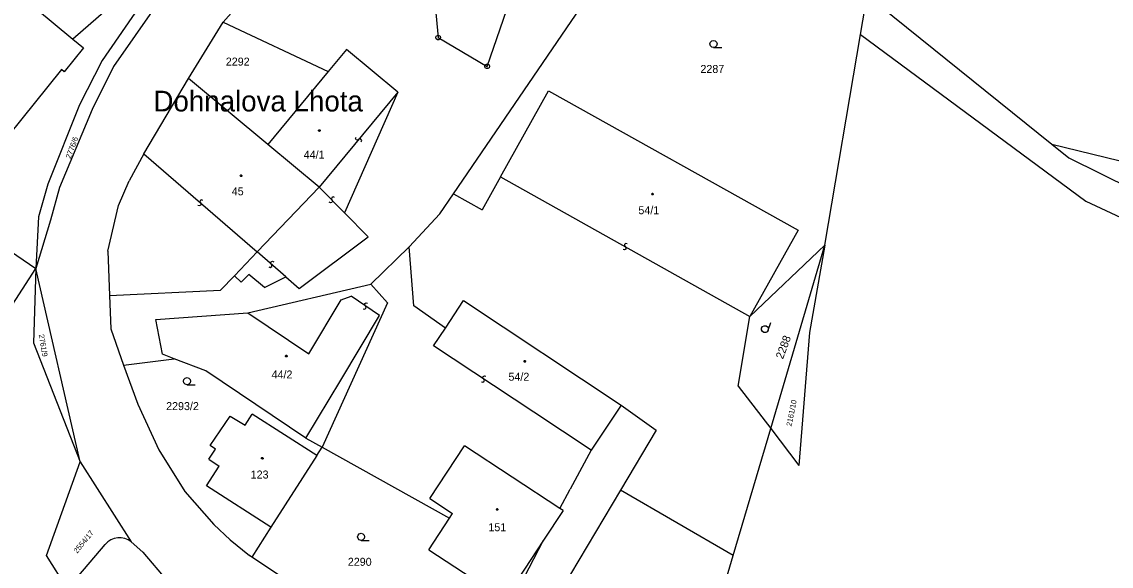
# Model space of a CAD drawing. Extents: x -747792 to -745414, y -1093712 to -1091463.
# Drawn here: x -746688.5 to -746572.8, y -1093115.1 to -1093057.2 of the extents above; entities that cross this region are included whole.
import ezdxf

# ---------------------------------------------------------------- set-up
doc = ezdxf.new("R2010")
doc.units = 0
for name, color, linetype in [('Pracovní_bod JDTM STC_VC', 7, 'Continuous'), ('Pracovní_bod JDTM STC_VC - výška', 7, 'Continuous'), ('Pracovní_bod JDTM STC_VC - číslo', 7, 'Continuous'), ('Pracovní_bod NN - výška', 7, 'Continuous'), ('Pracovní_bod polohopisu', 7, 'Continuous'), ('Pracovní_bod polohopisu - výška', 7, 'Continuous'), ('Pracovní_bod VN - výška', 7, 'Continuous')]:
    doc.layers.add(name, color=color, linetype=linetype)

msp = doc.modelspace()

# ---------------------------------------------------------------- linework, layer by layer
at = {"layer": 'Pracovní_bod JDTM STC_VC - výška'}
for points in [[(-746656.87, -1093068.71), (-746656.82, -1093068.72), (-746656.79, -1093068.76), (-746656.78, -1093068.79), (-746656.79, -1093068.83), (-746656.83, -1093068.87), (-746656.87, -1093068.88), (-746656.92, -1093068.86), (-746656.95, -1093068.83), (-746656.96, -1093068.79), (-746656.95, -1093068.75), (-746656.91, -1093068.71)], [(-746665.19, -1093073.51), (-746665.14, -1093073.52), (-746665.11, -1093073.56), (-746665.1, -1093073.59), (-746665.11, -1093073.64), (-746665.16, -1093073.67), (-746665.19, -1093073.68), (-746665.23, -1093073.66), (-746665.26, -1093073.63), (-746665.27, -1093073.59), (-746665.26, -1093073.54), (-746665.22, -1093073.51)], [(-746621.49, -1093075.46), (-746621.44, -1093075.47), (-746621.42, -1093075.51), (-746621.41, -1093075.54), (-746621.42, -1093075.58), (-746621.46, -1093075.62), (-746621.49, -1093075.62), (-746621.53, -1093075.61), (-746621.57, -1093075.58), (-746621.58, -1093075.54), (-746621.57, -1093075.5), (-746621.52, -1093075.46)], [(-746660.38, -1093092.67), (-746660.33, -1093092.68), (-746660.3, -1093092.72), (-746660.29, -1093092.75), (-746660.3, -1093092.79), (-746660.34, -1093092.83), (-746660.38, -1093092.83), (-746660.43, -1093092.82), (-746660.46, -1093092.79), (-746660.47, -1093092.75), (-746660.46, -1093092.71), (-746660.42, -1093092.67)], [(-746635.04, -1093093.23), (-746634.99, -1093093.24), (-746634.97, -1093093.28), (-746634.96, -1093093.31), (-746634.97, -1093093.35), (-746635.01, -1093093.39), (-746635.04, -1093093.4), (-746635.08, -1093093.38), (-746635.11, -1093093.35), (-746635.12, -1093093.31), (-746635.11, -1093093.27), (-746635.08, -1093093.23)], [(-746662.93, -1093103.53), (-746662.88, -1093103.54), (-746662.85, -1093103.58), (-746662.84, -1093103.61), (-746662.85, -1093103.66), (-746662.9, -1093103.69), (-746662.93, -1093103.7), (-746662.98, -1093103.68), (-746663.01, -1093103.65), (-746663.02, -1093103.61), (-746663.01, -1093103.56), (-746662.97, -1093103.53)], [(-746637.99, -1093108.96), (-746637.94, -1093108.97), (-746637.92, -1093109.01), (-746637.91, -1093109.04), (-746637.92, -1093109.08), (-746637.96, -1093109.12), (-746637.99, -1093109.12), (-746638.03, -1093109.11), (-746638.07, -1093109.08), (-746638.08, -1093109.04), (-746638.07, -1093109), (-746638.02, -1093108.96)]]:
    msp.add_lwpolyline(points, close=True, dxfattribs=at)
at = {"layer": 'Pracovní_bod JDTM STC_VC - číslo'}
for points in [[(-746615.01, -1093059.97), (-746615.2, -1093059.92), (-746615.33, -1093059.78), (-746615.39, -1093059.59), (-746615.33, -1093059.41), (-746615.2, -1093059.27), (-746615.01, -1093059.22), (-746614.82, -1093059.27), (-746614.69, -1093059.41), (-746614.64, -1093059.59), (-746614.69, -1093059.78), (-746614.82, -1093059.92), (-746615.01, -1093059.97), (-746614.14, -1093059.97)], [(-746609.19, -1093090), (-746609.3, -1093090.17), (-746609.47, -1093090.25), (-746609.66, -1093090.24), (-746609.82, -1093090.14), (-746609.91, -1093089.97), (-746609.9, -1093089.77), (-746609.8, -1093089.61), (-746609.62, -1093089.52), (-746609.43, -1093089.53), (-746609.27, -1093089.63), (-746609.18, -1093089.8), (-746609.19, -1093090), (-746608.92, -1093089.17)], [(-746670.93, -1093095.79), (-746671.12, -1093095.74), (-746671.26, -1093095.6), (-746671.31, -1093095.42), (-746671.26, -1093095.23), (-746671.12, -1093095.09), (-746670.93, -1093095.04), (-746670.74, -1093095.09), (-746670.6, -1093095.23), (-746670.56, -1093095.42), (-746670.6, -1093095.6), (-746670.74, -1093095.74), (-746670.93, -1093095.79), (-746670.06, -1093095.79)], [(-746652.44, -1093112.33), (-746652.63, -1093112.28), (-746652.76, -1093112.14), (-746652.82, -1093111.96), (-746652.76, -1093111.77), (-746652.63, -1093111.63), (-746652.44, -1093111.58), (-746652.25, -1093111.63), (-746652.11, -1093111.77), (-746652.07, -1093111.96), (-746652.11, -1093112.14), (-746652.25, -1093112.28), (-746652.44, -1093112.33), (-746651.57, -1093112.33)]]:
    msp.add_lwpolyline(points, dxfattribs=at)
at = {"layer": 'Pracovní_bod NN - výška'}
for points in [[(-746646, -1093040.57), (-746644.26, -1093058.92)], [(-746667.08, -1093057.29), (-746652.89, -1093041.3)], [(-746639.05, -1093061.97), (-746634.9, -1093049.93)], [(-746690.81, -1093052.63), (-746683.06, -1093059.07)], [(-746675.99, -1093052.89), (-746683.06, -1093059.07)], [(-746672.1, -1093052.41), (-746678.75, -1093061.97)], [(-746642.63, -1093075.5), (-746627.61, -1093053.49)], [(-746599.4, -1093058.58), (-746598.7, -1093054.4)], [(-746598.7, -1093054.4), (-746579.06, -1093070.24)], [(-746675.78, -1093055.31), (-746679.93, -1093061.36)], [(-746670.76, -1093063.27), (-746667.08, -1093057.29)], [(-746667.08, -1093057.29), (-746655.94, -1093062.51)], [(-746644.26, -1093058.92), (-746639.05, -1093061.97)], [(-746603.19, -1093080.96), (-746599.4, -1093058.58)], [(-746599.4, -1093058.58), (-746575.48, -1093076.3)], [(-746654, -1093060.17), (-746655.94, -1093062.51)], [(-746648.53, -1093064.7), (-746654, -1093060.17)], [(-746679.93, -1093061.36), (-746682.34, -1093066.05)], [(-746678.75, -1093061.97), (-746681.02, -1093066.55)], [(-746655.94, -1093062.51), (-746662.35, -1093070.26)], [(-746675.52, -1093071.26), (-746670.76, -1093063.27)], [(-746662.35, -1093070.26), (-746670.76, -1093063.27)], [(-746648.53, -1093064.7), (-746654.21, -1093077.52)], [(-746637.64, -1093073.72), (-746632.52, -1093064.56)], [(-746632.52, -1093064.56), (-746606.03, -1093079.37)], [(-746682.34, -1093066.05), (-746685.73, -1093074.49)], [(-746681.02, -1093066.55), (-746684.47, -1093074.84)], [(-746656.88, -1093074.79), (-746662.35, -1093070.26)], [(-746579.06, -1093070.24), (-746577.26, -1093071.69)], [(-746579.06, -1093070.24), (-746532.91, -1093081.49)], [(-746675.52, -1093071.26), (-746677.09, -1093074.14)], [(-746577.26, -1093071.69), (-746550.42, -1093084.98)], [(-746678.21, -1093076.74), (-746677.09, -1093074.14)], [(-746637.64, -1093073.72), (-746639.59, -1093077.2)], [(-746685.73, -1093074.49), (-746686.7, -1093077.95)], [(-746684.47, -1093074.84), (-746685.44, -1093078.3)], [(-746663.49, -1093081.69), (-746656.88, -1093074.79)], [(-746644.09, -1093077.64), (-746642.63, -1093075.5)], [(-746642.63, -1093075.5), (-746639.59, -1093077.2)], [(-746575.48, -1093076.3), (-746550.38, -1093088.03)], [(-746679.34, -1093081.62), (-746678.21, -1093076.74)], [(-746654.21, -1093077.52), (-746651.7, -1093080.07)], [(-746647.33, -1093081.13), (-746644.09, -1093077.64)], [(-746686.7, -1093077.95), (-746687, -1093083.45)], [(-746685.44, -1093078.3), (-746687, -1093083.45)], [(-746659.01, -1093085.57), (-746651.7, -1093080.07)], [(-746606.03, -1093079.37), (-746611.15, -1093088.53)], [(-746651.42, -1093085.1), (-746647.33, -1093081.13)], [(-746646.84, -1093087.43), (-746647.33, -1093081.13)], [(-746603.19, -1093080.96), (-746611.15, -1093088.53)], [(-746608.94, -1093100.45), (-746603.19, -1093080.96)], [(-746603.19, -1093080.96), (-746604.82, -1093090.26)], [(-746679.34, -1093081.62), (-746679.17, -1093086.32)], [(-746665.9, -1093084.21), (-746663.49, -1093081.69)], [(-746692.69, -1093092.24), (-746687, -1093083.45)], [(-746687, -1093083.45), (-746687.24, -1093091.34)], [(-746682.29, -1093103.98), (-746687, -1093083.45)], [(-746667.39, -1093085.76), (-746665.9, -1093084.21)], [(-746665.9, -1093084.21), (-746665.18, -1093084.9)], [(-746665.18, -1093084.9), (-746664.38, -1093084.07)], [(-746662.7, -1093085.46), (-746664.38, -1093084.07)], [(-746662.7, -1093085.46), (-746660.45, -1093084.32)], [(-746660.45, -1093084.32), (-746659.01, -1093085.57)], [(-746679.17, -1093086.32), (-746667.39, -1093085.76)], [(-746664.47, -1093088.16), (-746651.42, -1093085.1)], [(-746651.42, -1093085.1), (-746649.65, -1093087.09)], [(-746679.17, -1093086.32), (-746679.04, -1093089.86)], [(-746643.49, -1093089.77), (-746641.56, -1093086.86)], [(-746641.56, -1093086.86), (-746624.81, -1093097.97)], [(-746674.23, -1093088.88), (-746664.47, -1093088.16)], [(-746649.65, -1093087.09), (-746656.59, -1093102.43)], [(-746643.49, -1093089.77), (-746646.84, -1093087.43)], [(-746673.55, -1093092.55), (-746674.23, -1093088.88)], [(-746612.39, -1093095.93), (-746611.15, -1093088.53)], [(-746679.04, -1093089.86), (-746677.68, -1093093.71)], [(-746604.82, -1093090.26), (-746605.95, -1093104.36)], [(-746687.24, -1093091.34), (-746682.29, -1093103.98)], [(-746672.31, -1093093.03), (-746673.55, -1093092.55)], [(-746677.68, -1093093.71), (-746672.31, -1093093.03)], [(-746677.68, -1093093.71), (-746676.17, -1093097.87)], [(-746668.95, -1093094.33), (-746672.31, -1093093.03)], [(-746658.31, -1093101.47), (-746668.95, -1093094.33)], [(-746612.39, -1093095.93), (-746608.94, -1093100.45)], [(-746676.17, -1093097.87), (-746673.91, -1093102.7)], [(-746624.81, -1093097.97), (-746627.99, -1093102.76)], [(-746624.81, -1093097.97), (-746621.1, -1093100.62)], [(-746668.48, -1093102.26), (-746666.36, -1093099.13)], [(-746666.36, -1093099.13), (-746664.77, -1093100.09)], [(-746664.77, -1093100.09), (-746664.02, -1093098.92)], [(-746657.16, -1093103.33), (-746664.02, -1093098.92)], [(-746621.1, -1093100.62), (-746624.9, -1093107.01)], [(-746612.92, -1093113.93), (-746608.94, -1093100.45)], [(-746608.94, -1093100.45), (-746605.95, -1093104.36)], [(-746658.31, -1093101.47), (-746656.59, -1093102.43)], [(-746673.91, -1093102.7), (-746671.17, -1093107.14)], [(-746668.63, -1093103.72), (-746667.91, -1093102.64)], [(-746667.91, -1093102.64), (-746668.48, -1093102.26)], [(-746657.16, -1093103.33), (-746656.59, -1093102.43)], [(-746656.59, -1093102.43), (-746643.05, -1093109.98)], [(-746645.14, -1093107.88), (-746641.47, -1093102.28)], [(-746631.32, -1093108.94), (-746641.47, -1093102.28)], [(-746627.99, -1093102.76), (-746630.25, -1093106.88)], [(-746685.84, -1093113.95), (-746682.29, -1093103.98)], [(-746682.29, -1093103.98), (-746676.87, -1093112.49)], [(-746668.63, -1093103.72), (-746667.52, -1093104.44)], [(-746657.16, -1093103.33), (-746662.02, -1093110.94)], [(-746668.87, -1093106.54), (-746667.52, -1093104.44)], [(-746662.02, -1093110.94), (-746668.87, -1093106.54)], [(-746671.17, -1093107.14), (-746668.1, -1093110.63)], [(-746624.9, -1093107.01), (-746639.04, -1093130.78)], [(-746631.32, -1093108.94), (-746630.25, -1093106.88)], [(-746612.92, -1093113.93), (-746624.9, -1093107.01)], [(-746645.14, -1093107.88), (-746642.72, -1093109.47)], [(-746630.99, -1093109.15), (-746631.32, -1093108.94)], [(-746645.26, -1093113.33), (-746643.05, -1093109.98)], [(-746643.05, -1093109.98), (-746642.72, -1093109.47)], [(-746630.99, -1093109.15), (-746633.07, -1093112.31)], [(-746668.1, -1093110.63), (-746666.35, -1093112.27)], [(-746662.02, -1093110.94), (-746664.05, -1093114.11)], [(-746676.87, -1093112.49), (-746675.62, -1093113.6), (-746673.04, -1093116.62)], [(-746666.35, -1093112.27), (-746664.29, -1093113.95)], [(-746641.71, -1093129), (-746633.07, -1093112.31)], [(-746633.07, -1093112.31), (-746636.44, -1093117.45)], [(-746683.64, -1093117.48), (-746679.61, -1093112.76)], [(-746645.26, -1093113.33), (-746640.63, -1093116.36)], [(-746683.64, -1093117.48), (-746685.84, -1093113.95)], [(-746664.05, -1093114.11), (-746664.29, -1093113.95)], [(-746641.71, -1093129), (-746664.05, -1093114.11)], [(-746616.34, -1093125.52), (-746612.92, -1093113.93)]]:
    msp.add_lwpolyline(points, dxfattribs=at)
msp.add_arc((-746678.1, -1093114.04), 1.98, 51.5536, 139.7019, dxfattribs=at)
at = {"layer": 'Pracovní_bod polohopisu'}
for points in [[(-746683.06, -1093059.07), (-746681.93, -1093060)], [(-746681.93, -1093060), (-746683.97, -1093062.54)], [(-746684.28, -1093062.29), (-746689.94, -1093069.35)], [(-746683.97, -1093062.54), (-746684.28, -1093062.29)], [(-746648.53, -1093064.7), (-746656.88, -1093074.79)], [(-746652.43, -1093070), (-746652.37, -1093069.86), (-746652.46, -1093069.71), (-746652.6, -1093069.68), (-746652.82, -1093069.81), (-746652.97, -1093069.77), (-746653.04, -1093069.62), (-746652.98, -1093069.49)], [(-746675.52, -1093071.26), (-746663.49, -1093081.69)], [(-746637.64, -1093073.72), (-746611.15, -1093088.53)], [(-746656.88, -1093074.79), (-746654.21, -1093077.52)], [(-746697.68, -1093076.15), (-746687, -1093083.45)], [(-746669.24, -1093076.21), (-746669.39, -1093076.15), (-746669.53, -1093076.23), (-746669.57, -1093076.37), (-746669.44, -1093076.59), (-746669.49, -1093076.74), (-746669.64, -1093076.8), (-746669.77, -1093076.74)], [(-746655.26, -1093075.91), (-746655.4, -1093075.84), (-746655.55, -1093075.9), (-746655.6, -1093076.05), (-746655.49, -1093076.28), (-746655.55, -1093076.42), (-746655.7, -1093076.47), (-746655.83, -1093076.4)], [(-746624.19, -1093080.81), (-746624.35, -1093080.78), (-746624.47, -1093080.89), (-746624.48, -1093081.04), (-746624.31, -1093081.23), (-746624.33, -1093081.38), (-746624.46, -1093081.47), (-746624.6, -1093081.44)], [(-746660.45, -1093084.32), (-746663.49, -1093081.69)], [(-746662.23, -1093083.27), (-746662.09, -1093083.33), (-746661.94, -1093083.25), (-746661.91, -1093083.11), (-746662.03, -1093082.89), (-746661.99, -1093082.74), (-746661.84, -1093082.68), (-746661.71, -1093082.74)], [(-746657.98, -1093092.5), (-746654.56, -1093086.76)], [(-746654.56, -1093086.76), (-746653.5, -1093086.39)], [(-746650.47, -1093088.45), (-746653.5, -1093086.39)], [(-746664.47, -1093088.16), (-746657.98, -1093092.5)], [(-746652.22, -1093087.72), (-746652.06, -1093087.76), (-746651.93, -1093087.66), (-746651.91, -1093087.51), (-746652.06, -1093087.31), (-746652.03, -1093087.16), (-746651.89, -1093087.08), (-746651.75, -1093087.12)], [(-746654.59, -1093095.3), (-746650.47, -1093088.45)], [(-746644.74, -1093091.65), (-746643.49, -1093089.77)], [(-746634.1, -1093098.71), (-746644.74, -1093091.65)], [(-746639.65, -1093095.48), (-746639.5, -1093095.52), (-746639.36, -1093095.42), (-746639.34, -1093095.27), (-746639.5, -1093095.07), (-746639.47, -1093094.92), (-746639.33, -1093094.84), (-746639.19, -1093094.88)], [(-746658.31, -1093101.47), (-746654.59, -1093095.3)], [(-746627.99, -1093102.76), (-746634.1, -1093098.71)]]:
    msp.add_lwpolyline(points, dxfattribs=at)
at = {"layer": 'Pracovní_bod VN - výška'}
for points in [[(-746644.19, -1093058.68), (-746644.06, -1093058.77), (-746644.01, -1093058.92), (-746644.06, -1093059.06), (-746644.19, -1093059.16), (-746644.33, -1093059.16), (-746644.46, -1093059.06), (-746644.51, -1093058.92), (-746644.46, -1093058.77), (-746644.33, -1093058.68)], [(-746638.98, -1093061.73), (-746638.85, -1093061.82), (-746638.8, -1093061.97), (-746638.85, -1093062.11), (-746638.98, -1093062.21), (-746639.12, -1093062.21), (-746639.25, -1093062.11), (-746639.3, -1093061.97), (-746639.25, -1093061.82), (-746639.12, -1093061.73)]]:
    msp.add_lwpolyline(points, close=True, dxfattribs=at)
for points in [[(-746644.29, -1093058.92), (-746644.23, -1093058.92)], [(-746639.08, -1093061.97), (-746639.03, -1093061.97)]]:
    msp.add_lwpolyline(points, dxfattribs=at)

# ---------------------------------------------------------------- texts
at = {"layer": 'Pracovní_bod JDTM STC_VC'}
for s, p in [('2292', (-746666.81, -1093061.89)), ('2287', (-746616.4, -1093062.67)), ('44/1', (-746658.54, -1093071.78)), ('45', (-746666.18, -1093075.67)), ('54/1', (-746622.99, -1093077.68)), ('44/2', (-746661.95, -1093095.13)), ('54/2', (-746636.79, -1093095.37)), ('2293/2', (-746673.15, -1093098.49)), ('123', (-746664.17, -1093105.76)), ('151', (-746638.92, -1093111.36)), ('2290', (-746653.85, -1093115.03))]:
    msp.add_text(s, height=0.85, dxfattribs=at).set_placement(p)
for s, height, rotation, p in [('2776/6', 0.57, 69.6717, (-746683.31, -1093071.83)), ('2761/9', 0.57, 279.4888, (-746686.68, -1093090.48)), ('2288', 0.85, 69.6144, (-746607.64, -1093093.13)), ('2161/10', 0.57, 78.7244, (-746606.73, -1093100.25)), ('2554/17', 0.57, 50.7068, (-746682.6, -1093113.76))]:
    msp.add_text(s, height=height, rotation=rotation, dxfattribs=at).set_placement(p)
at = {"layer": 'Pracovní_bod polohopisu - výška'}
msp.add_text('Dohnalova Lhota', height=2.2, dxfattribs=at).set_placement((-746674.5, -1093066.76))

doc.saveas('drawing.dxf')
